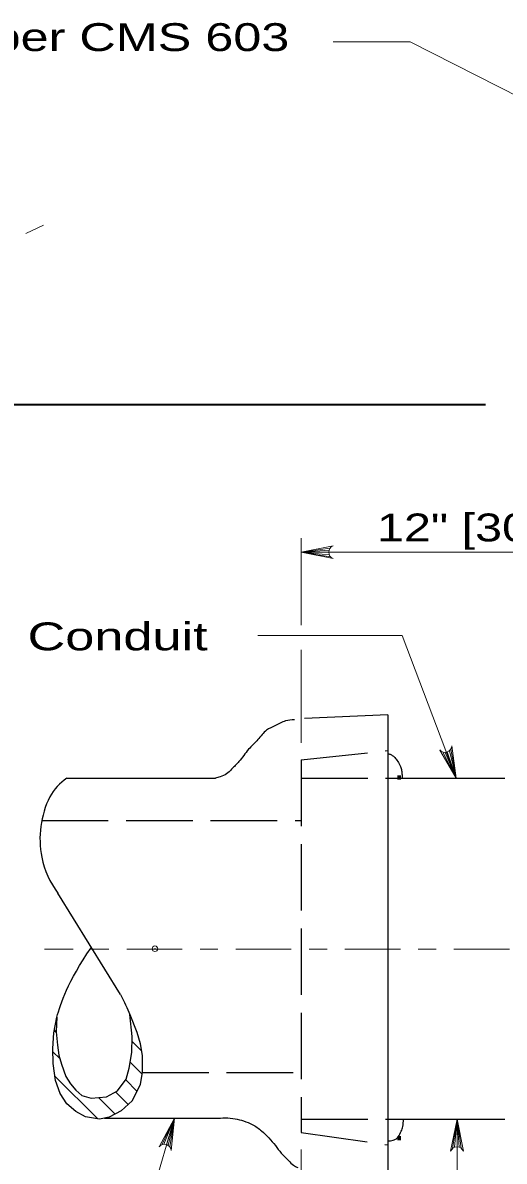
# Model space of a CAD drawing. Extents: x 1083.1 to 1117.1, y 719.4 to 741.4.
# Drawn here: x 1096.96 to 1099.65, y 725.28 to 731.65 of the extents above; entities that cross this region are included whole.
import ezdxf

# ---------------------------------------------------------------- set-up
doc = ezdxf.new("R2010")
doc.units = 0
doc.header["$LTSCALE"] = 0.062
doc.header["$PDMODE"] = 32
doc.header["$PDSIZE"] = 0.031
doc.linetypes.add('DOT_DASHED', pattern=[7.7, 5, -1.2, 0.3, -1.2])
doc.linetypes.add('LONG_DASHED', pattern=[7.5, 6, -1.5])
doc.layers.add('1', color=7, linetype='Continuous', lineweight=13)

msp = doc.modelspace()

# ---------------------------------------------------------------- linework, layer by layer
at = {"layer": '1'}
for p, q in [((1097.0725, 730.51692), (1096.97217, 730.46867)), ((1098.51258, 728.41792), (1098.51258, 728.76492)), ((1098.67383, 728.70833), (1098.51258, 728.68575)), ((1098.66833, 728.69717), (1098.51258, 728.68575)), ((1098.66667, 728.68575), (1098.51258, 728.68575)), ((1098.6695, 728.67133), (1098.51258, 728.68575)), ((1098.67567, 728.66083), (1098.51258, 728.68575)), ((1098.51258, 728.68575), (1100.9615, 728.68575)), ((1098.51258, 728.27825), (1098.51258, 728.41792)), ((1099.07692, 728.22025), (1098.27083, 728.22025)), ((1099.36833, 727.45117), (1099.07692, 728.22025)), ((1098.51258, 727.61917), (1098.51258, 728.13883)), ((1099.30483, 727.56742), (1099.37825, 727.42217)), ((1099.31717, 727.56583), (1099.37825, 727.42217)), ((1099.3285, 727.568), (1099.37825, 727.42217)), ((1099.34125, 727.57533), (1099.37825, 727.42217)), ((1099.34917, 727.5845), (1099.37825, 727.42217)), ((1097.55733, 726.0935), (1097.55558, 726.09508)), ((1097.56342, 726.07775), (1097.55675, 726.0845)), ((1097.142, 726.00267), (1097.13292, 726.01192)), ((1097.14483, 726.05208), (1097.14133, 726.05567)), ((1097.14217, 725.99883), (1097.13233, 726.00875)), ((1097.61933, 725.89617), (1097.56692, 725.94867)), ((1097.16342, 725.85225), (1097.12467, 725.89092)), ((1097.62225, 725.76767), (1097.55717, 725.833)), ((1097.37467, 725.51458), (1097.136, 725.75408)), ((1097.59375, 725.67092), (1097.53175, 725.73325)), ((1097.47242, 725.54175), (1097.37958, 725.635)), ((1097.54433, 725.59508), (1097.474, 725.66567)), ((1097.73283, 725.36983), (1097.80425, 725.5185)), ((1097.74458, 725.37267), (1097.80425, 725.5185)), ((1097.75933, 725.37117), (1097.80425, 725.5185)), ((1097.76967, 725.36625), (1097.80425, 725.5185)), ((1097.77875, 725.35783), (1097.80425, 725.5185)), ((1099.35875, 725.34958), (1099.38367, 725.51267)), ((1099.36917, 725.35575), (1099.38367, 725.51267)), ((1099.38367, 723.623), (1099.38367, 725.51267)), ((1099.38367, 725.35858), (1099.38367, 725.51267)), ((1099.39508, 725.35692), (1099.38367, 725.51267)), ((1099.40625, 725.3515), (1099.38367, 725.51267)), ((1097.79517, 725.48875), (1097.54492, 724.64525)), ((1098.51258, 725.34433), (1098.51258, 721.90717))]:
    msp.add_line(p, q, dxfattribs=at)
at = {"layer": '1', "lineweight": 35}
for p, q in [((1096.79417, 729.51175), (1099.41317, 729.51175)), ((1099.41317, 729.51175), (1099.54292, 729.51175))]:
    msp.add_line(p, q, dxfattribs=at)
at = {"layer": '1', "lineweight": 25}
for p, q in [((1098.99725, 727.77608), (1098.53183, 727.75617)), ((1098.99725, 727.77608), (1098.99725, 725.21108)), ((1097.20208, 727.42125), (1098.03317, 727.42125)), ((1098.99725, 727.42125), (1099.65058, 727.42125)), ((1097.50208, 726.21167), (1097.1525, 726.77842)), ((1097.41233, 725.5185), (1098.03317, 725.5185)), ((1098.99725, 725.51267), (1099.65058, 725.51267))]:
    msp.add_line(p, q, dxfattribs=at)
at = {"layer": '1', "linetype": 'LONG_DASHED', "lineweight": 25}
for p, q in [((1098.51258, 727.52425), (1098.99725, 727.57567)), ((1098.51258, 727.52425), (1098.51258, 725.43933)), ((1098.51258, 727.42125), (1098.99725, 727.42125)), ((1097.06225, 727.18458), (1098.51258, 727.18458)), ((1097.62342, 725.77467), (1098.51258, 725.77467)), ((1098.51258, 725.51267), (1098.99725, 725.51267)), ((1098.51258, 725.43933), (1098.99725, 725.369))]:
    msp.add_line(p, q, dxfattribs=at)
at = {"layer": '1', "linetype": 'DOT_DASHED'}
msp.add_line((1101.50683, 726.46408), (1097.07783, 726.46408), dxfattribs=at)
at = {"layer": '1'}
for points in [[(1100.47958, 730.85158), (1099.12242, 731.54225), (1098.69108, 731.54225)], [(1098.69067, 728.65017), (1098.51258, 728.68575), (1098.69067, 728.72142)], [(1099.3545, 727.60217), (1099.37825, 727.42217), (1099.28708, 727.57908)], [(1097.55525, 726.09867), (1097.59325, 726.00083), (1097.61217, 725.93708), (1097.62425, 725.86858), (1097.62383, 725.77692), (1097.61158, 725.70717), (1097.56725, 725.6165), (1097.50692, 725.55992), (1097.43967, 725.52433), (1097.38483, 725.51267), (1097.30625, 725.527), (1097.25225, 725.55708), (1097.20217, 725.59842), (1097.16425, 725.65633), (1097.13917, 725.72933), (1097.12667, 725.82417), (1097.12408, 725.90917), (1097.12992, 725.99617), (1097.14667, 726.08375)], [(1097.71825, 725.35858), (1097.80425, 725.5185), (1097.78633, 725.33783)], [(1099.34808, 725.33458), (1099.38367, 725.51267), (1099.41925, 725.33458)]]:
    msp.add_lwpolyline(points, dxfattribs=at)
at = {"layer": '1', "lineweight": 25}
for points in [[(1097.55525, 726.09867), (1097.59325, 726.00083), (1097.61217, 725.93708), (1097.62425, 725.86858), (1097.62383, 725.77692), (1097.61158, 725.70717), (1097.56725, 725.6165), (1097.50692, 725.55992), (1097.43967, 725.52433), (1097.38483, 725.51267), (1097.30625, 725.527), (1097.25225, 725.55708), (1097.20217, 725.59842), (1097.16425, 725.65633), (1097.13917, 725.72933), (1097.12667, 725.82417), (1097.12408, 725.90917), (1097.12992, 725.99617), (1097.14667, 726.08375)], [(1097.14667, 726.08375), (1097.14192, 726.00117), (1097.14917, 725.92783), (1097.15775, 725.87183), (1097.17208, 725.82142), (1097.19633, 725.75242), (1097.22358, 725.71067), (1097.25225, 725.67467), (1097.28667, 725.646), (1097.33817, 725.63158), (1097.42408, 725.63867), (1097.48583, 725.67183), (1097.53442, 725.73658), (1097.55167, 725.79842), (1097.56592, 725.88617), (1097.56742, 725.97683), (1097.55525, 726.09867)], [(1097.14667, 726.08375), (1097.14192, 726.00117), (1097.14917, 725.92783), (1097.15775, 725.87183), (1097.17208, 725.82142), (1097.19633, 725.75242), (1097.22358, 725.71067), (1097.25225, 725.67467), (1097.28667, 725.646), (1097.33817, 725.63158), (1097.42408, 725.63867), (1097.48583, 725.67183), (1097.53442, 725.73658), (1097.55167, 725.79842), (1097.56592, 725.88617), (1097.56742, 725.97683), (1097.55525, 726.09867)]]:
    msp.add_lwpolyline(points, dxfattribs=at)
at = {"layer": '1'}
for centre, major_axis, start_param, end_param in [((1098.7051, 728.68579), (-0.03843, 0), 5.0978942, 7.4685073), ((1099.31609, 727.60431), (-0.03822, -0.00395), 0.6112543, 2.9818674), ((1097.74806, 725.33441), (0.03843, 0), 0.0892914, 2.4599045), ((1099.38367, 725.32017), (0.03843, 0), 0.3855052, 2.7561184)]:
    msp.add_ellipse(centre, major_axis=major_axis, ratio=0.999895, start_param=start_param, end_param=end_param, dxfattribs=at)
at = {"layer": '1', "lineweight": 25}
for centre, major_axis, start_param, end_param in [((1097.38487, 727.15775), (0, 0.32118), 0.608535, 1.0523476), ((1097.58217, 727.08079), (0, -0.53235), 4.2528342, 4.9042115), ((1097.53161, 727.07248), (0, -0.48097), 4.9073919, 5.370128)]:
    msp.add_ellipse(centre, major_axis=major_axis, ratio=0.995779, start_param=start_param, end_param=end_param, dxfattribs=at)
for points in [[(1098.47592, 727.74858), (1098.42458, 727.74158), (1098.36592, 727.71475), (1098.31942, 727.68983), (1098.27033, 727.63733), (1098.21833, 727.583), (1098.16417, 727.514), (1098.12333, 727.47175), (1098.09575, 727.4455), (1098.059, 727.42883), (1098.03317, 727.42125)], [(1098.99833, 727.55925), (1099.01433, 727.55342), (1099.02833, 727.54375), (1099.04333, 727.52825), (1099.06025, 727.50208), (1099.068, 727.48708), (1099.07383, 727.46483), (1099.07625, 727.43967), (1099.07767, 727.42175)], [(1098.03317, 725.5185), (1098.14317, 725.51567), (1098.19067, 725.50333), (1098.23908, 725.48433), (1098.29133, 725.44725), (1098.36833, 725.3655), (1098.40092, 725.32367), (1098.44167, 725.28142), (1098.46925, 725.25517), (1098.49375, 725.24242)], [(1098.99717, 725.39225), (1099.01167, 725.39267), (1099.02675, 725.39608), (1099.04458, 725.40383), (1099.05483, 725.415), (1099.07225, 725.44642), (1099.08, 725.47167), (1099.08433, 725.51325)]]:
    msp.add_spline(points, degree=3, dxfattribs=at)
for points in [[(1097.14667, 726.08375), (1097.16633, 726.16), (1097.2075, 726.28242), (1097.338, 726.4725)], [(1097.50208, 726.21167), (1097.523, 726.17008), (1097.5405, 726.13242), (1097.55525, 726.09867)]]:
    msp.add_open_spline(points, degree=3, dxfattribs=at)
at = {"layer": '1'}
msp.add_point((1097.69492, 726.46692), dxfattribs=at)

# ---------------------------------------------------------------- texts
for s, width, p in [('per CMS 603', 1.35, (1096.78708, 731.49033)), ('12" [300] min.', 1.3, (1098.93617, 728.74642)), ('6" [150] CMS 603 Conduit', 1.4, (1094.60608, 728.13692))]:
    msp.add_text(s, height=0.156, dxfattribs=dict(at, width=width)).set_placement(p)
for p in [(1099.03125, 727.41392), (1099.03167, 725.39492)]:
    msp.add_text('.', height=0.156, dxfattribs=at).set_placement(p)

doc.saveas('drawing.dxf')
